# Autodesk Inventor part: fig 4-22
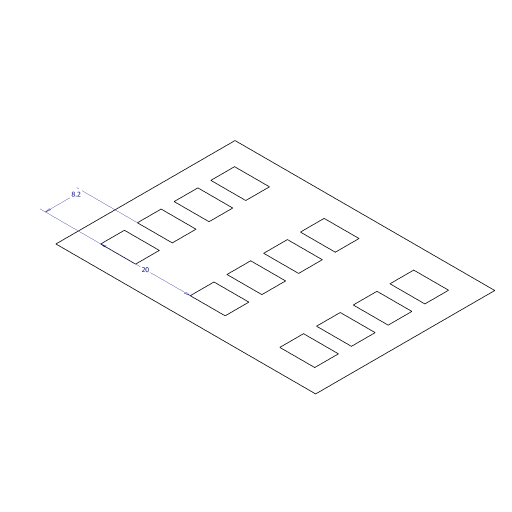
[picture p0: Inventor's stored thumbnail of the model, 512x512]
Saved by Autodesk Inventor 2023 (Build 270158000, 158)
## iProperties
Created: 2004-05
Part Number: fig 4-22
Document SubType Name: Modeling
Designer: CADCIM Technologies
Manufacturer: Standard
Standards Organization: Custom
Density: 1 g/cm^3
Material: Generic
Appearance: Default
Author: CADCIM Technologies
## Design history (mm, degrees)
sketch "Sketch1"
  geometry: L1 (7.752, 6.176)-(65.752, 6.176); L2 (65.752, 6.176)-(65.752, 46.176); L3 (65.752, 46.176)-(7.752, 46.176); L4 (7.752, 46.176)-(7.752, 6.176); L5 (12.752, 11.176)-(20.543, 11.176); L6 (20.543, 11.176)-(20.543, 16.473); L7 (20.543, 16.473)-(12.752, 16.473); L8 (12.752, 16.473)-(12.752, 11.176); L9 (32.752, 11.176)-(40.543, 11.176); L10 (40.543, 11.176)-(40.543, 16.473); L11 (40.543, 16.473)-(32.752, 16.473); L12 (32.752, 16.473)-(32.752, 11.176); L13 (52.752, 11.176)-(60.543, 11.176); L14 (60.543, 11.176)-(60.543, 16.473); L15 (60.543, 16.473)-(52.752, 16.473); L16 (52.752, 16.473)-(52.752, 11.176); L17 (12.752, 19.376)-(20.543, 19.376); L18 (20.543, 19.376)-(20.543, 24.673); L19 (20.543, 24.673)-(12.752, 24.673); L20 (12.752, 24.673)-(12.752, 19.376); L21 (32.752, 19.376)-(40.543, 19.376); L22 (40.543, 19.376)-(40.543, 24.673); L23 (40.543, 24.673)-(32.752, 24.673); L24 (32.752, 24.673)-(32.752, 19.376); L25 (52.752, 19.376)-(60.543, 19.376); L26 (60.543, 19.376)-(60.543, 24.673); L27 (60.543, 24.673)-(52.752, 24.673); L28 (52.752, 24.673)-(52.752, 19.376); L29 (12.752, 27.576)-(20.543, 27.576); L30 (20.543, 27.576)-(20.543, 32.873); L31 (20.543, 32.873)-(12.752, 32.873); L32 (12.752, 32.873)-(12.752, 27.576); L33 (32.752, 27.576)-(40.543, 27.576); L34 (40.543, 27.576)-(40.543, 32.873); L35 (40.543, 32.873)-(32.752, 32.873); L36 (32.752, 32.873)-(32.752, 27.576); L37 (52.752, 27.576)-(60.543, 27.576); L38 (60.543, 27.576)-(60.543, 32.873); L39 (60.543, 32.873)-(52.752, 32.873); L40 (52.752, 32.873)-(52.752, 27.576); L41 (12.752, 35.776)-(20.543, 35.776); L42 (20.543, 35.776)-(20.543, 41.073); L43 (20.543, 41.073)-(12.752, 41.073); L44 (12.752, 41.073)-(12.752, 35.776); L45 (32.752, 35.776)-(40.543, 35.776); L46 (40.543, 35.776)-(40.543, 41.073); L47 (40.543, 41.073)-(32.752, 41.073); L48 (32.752, 41.073)-(32.752, 35.776); L49 (52.752, 35.776)-(60.543, 35.776); L50 (60.543, 35.776)-(60.543, 41.073); L51 (60.543, 41.073)-(52.752, 41.073); L52 (52.752, 41.073)-(52.752, 35.776)
  constraints: 104 end point, 4 parallel, 3 horizontal, 2 perpendicular, 1 vertical, 88 other
  dimensions: "d14" = 20 distance of L5.start L9.start; "d17" = 8.2 distance of L5.start L17.start
